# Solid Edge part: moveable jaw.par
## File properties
Accuracy: 0.99
Title: Moveable Jaw
Author: Robert a Rhodes jr
Template: Normal.par
Last saved by: TIET
Revision: 14
Application: Solid Edge
Material: iron
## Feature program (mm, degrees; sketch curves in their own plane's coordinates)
sketch for "unnamed Protrusion 1" plane through (0, 0, 0) normal (0, -1, 0) x-axis (1, 0, 0)
  line (-36.5256, 25.2528) -> (-36.5256, -34.7472)
  line (-36.5256, -34.7472) -> (-33.0256, -34.7472)
  line (-33.0256, -34.7472) -> (-33.0256, -32.2472)
  line (-33.0256, -32.2472) -> (-30.5256, -32.2472)
  line (-30.5256, -32.2472) -> (-30.5256, -29.7472)
  line (-30.5256, -29.7472) -> (-28.0256, -29.7472)
  line (-28.0256, -29.7472) -> (-28.0256, -27.2472)
  line (-28.0256, -27.2472) -> (-25.5256, -27.2472)
  line (-25.5256, -27.2472) -> (-25.5256, -24.7472)
  line (-25.5256, -24.7472) -> (-23.0256, -24.7472)
  line (-23.0256, -24.7472) -> (-23.0256, -22.2472)
  line (-23.0256, -22.2472) -> (-20.5256, -22.2472)
  line (-20.5256, -22.2472) -> (-20.5256, -19.7472)
  line (-20.5256, -19.7472) -> (-18.0256, -19.7472)
  line (-18.0256, -22.2472) -> (-18.0256, -19.7472)
  line (-15.5256, -22.2472) -> (-18.0256, -22.2472)
  line (-15.5256, -24.7472) -> (-15.5256, -22.2472)
  line (-13.0256, -24.7472) -> (-15.5256, -24.7472)
  line (-13.0256, -27.2472) -> (-13.0256, -24.7472)
  line (-10.5256, -27.2472) -> (-13.0256, -27.2472)
  line (-10.5256, -29.7472) -> (-10.5256, -27.2472)
  line (-8.0256, -29.7472) -> (-10.5256, -29.7472)
  line (-8.0256, -32.2472) -> (-8.0256, -29.7472)
  line (-5.5256, -32.2472) -> (-8.0256, -32.2472)
  line (-5.5256, -34.7472) -> (-5.5256, -32.2472)
  line (-2.0256, -34.7472) -> (-5.5256, -34.7472)
  line (-2.0256, -34.7472) -> (-2.0256, 25.2528)
  line (-2.0256, 25.2528) -> (-36.5256, 25.2528)
extrude "unnamed Protrusion 1" add finite 18 along -normal
sketch for "Hole_1" plane through (-19.2756, 9, 25.2528) normal (0, 0, 1) x-axis (1, 0, 0)
  hole centre (0, 0) bore radius 6
hole "Hole_1" diameter 12 finite  VBottomAngle = 118 deg
sketch for "Hole_2" plane through (-2.0256, 9, -4.7472) normal (1, 0, 0) x-axis (0, 1, 0)
  hole centre (0, 23) bore radius 4.5
hole "Hole_2" diameter 9 through
chamfer "Chamfer_1" setback 2
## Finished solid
Body 1: solid body, 38 faces, 98 edges, 60 vertices.
  Faces by surface: plane 34, cylinder 3, cone 1
  Edges by curve: line 92, circle 4, intersection 2
Bounding box of the edges (mm): 34.500 x 18.000 x 60.000, from (-36.5256, 0, -34.7472) to (-2.0256, 18, 25.2528).
Cylindrical faces by radius (mm): R4.5 x2, R6 x1
Conical faces (half-angle, radius in mm at the cone's reference point): 59 deg R6 x1
Planar faces by outward normal: +x 7, +y 1, +z 1, -x 7, -y 1, -z 13, oblique 4
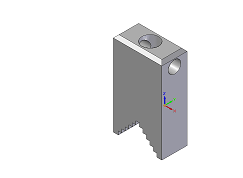
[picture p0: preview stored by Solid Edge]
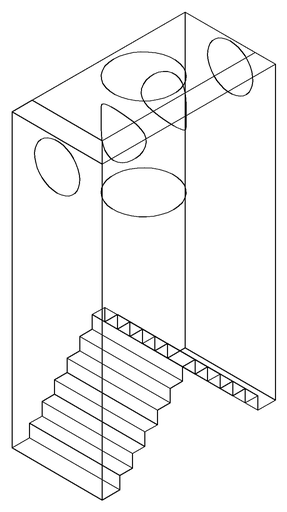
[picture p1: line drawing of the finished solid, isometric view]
